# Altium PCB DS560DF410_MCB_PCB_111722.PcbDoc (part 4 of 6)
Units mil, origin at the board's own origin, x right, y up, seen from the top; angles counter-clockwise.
Board outline 5500 x 5000 mil, 6 copper layers (Top Layer, L2_GND1, L3_SIG1, L4_PWR1, L5_GND2, Bottom Layer), stack 61.748 mil thick; 297 components, 231 nets, 1236 pads, 998 vias.
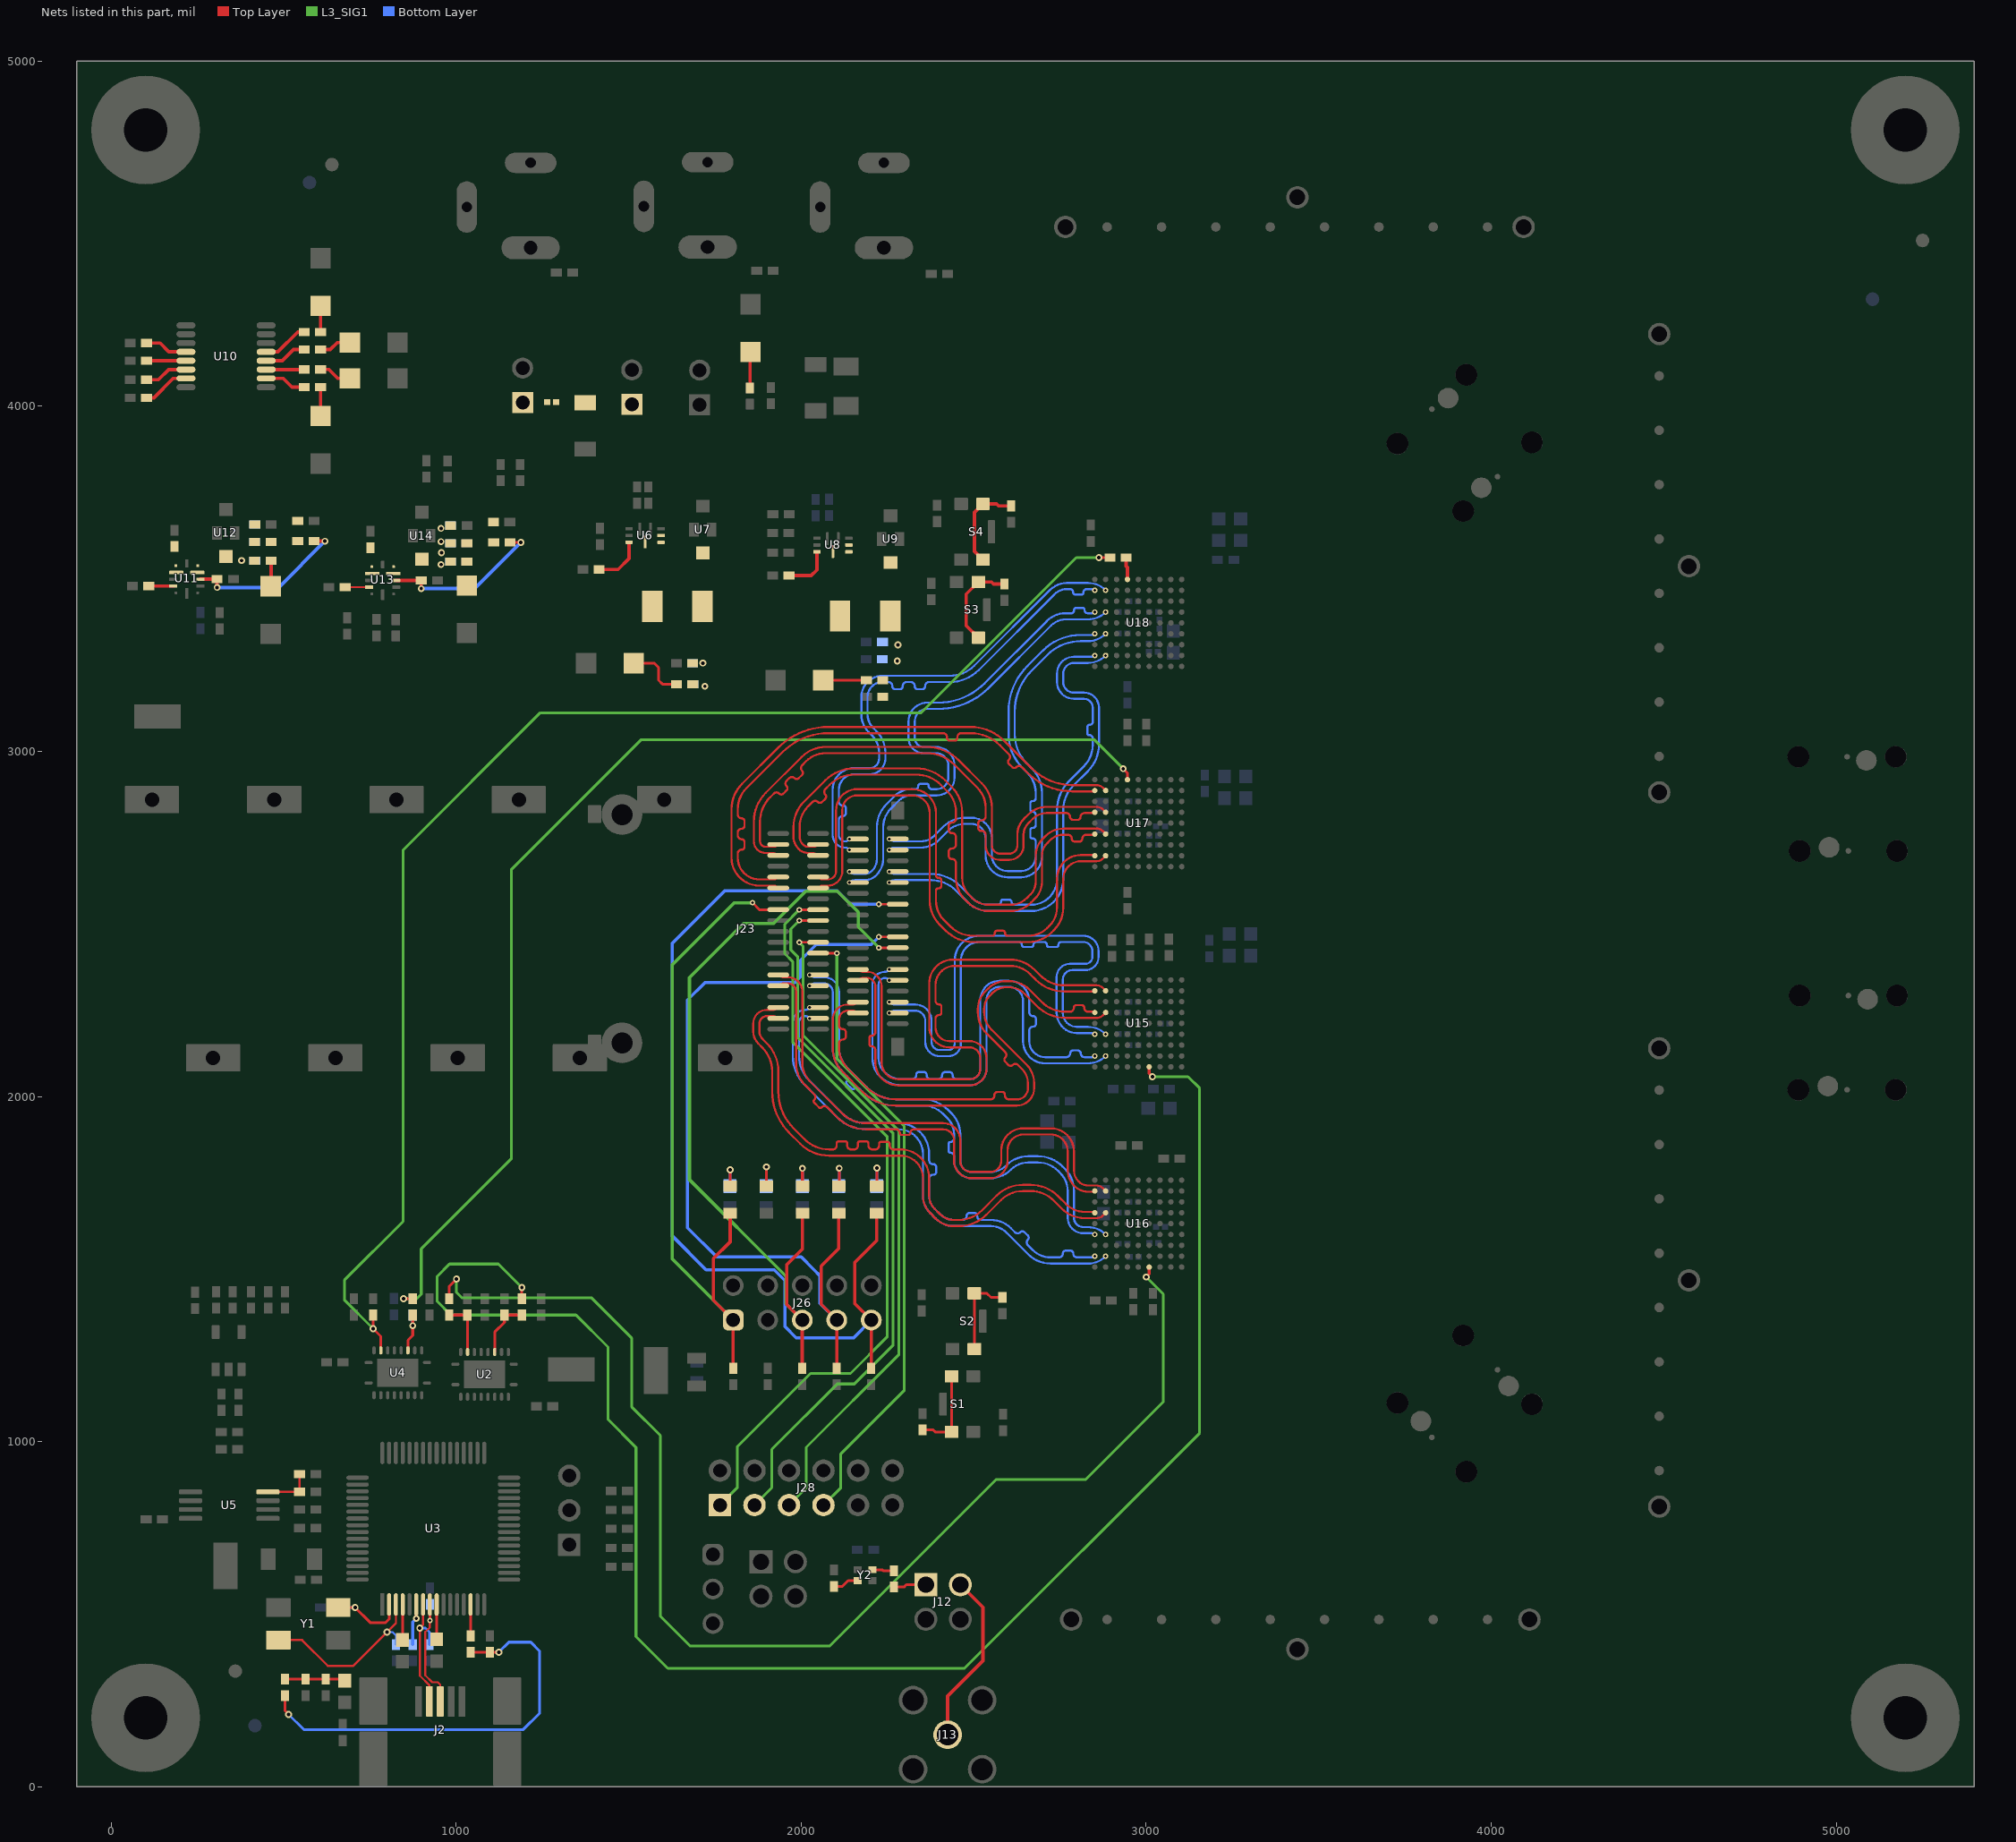
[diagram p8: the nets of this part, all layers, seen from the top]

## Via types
v1: diameter 20, hole 10, Top Layer to Bottom Layer, 380 vias
v2: diameter 24, hole 12, Top Layer to Bottom Layer, tented both sides, 226 vias
v3: diameter 20, hole 10, Top Layer to Bottom Layer, tented both sides, 162 vias
v4: diameter 14, hole 8.1, Top Layer to Bottom Layer, tented both sides, 88 vias
v5: diameter 16, hole 8.1, Top Layer to Bottom Layer, tented both sides, 84 vias
v6: diameter 16, hole 8, Top Layer to Bottom Layer, tented both sides, 34 vias
v7: diameter 15, hole 8.1, Top Layer to Bottom Layer, tented both sides, 16 vias
v8: diameter 19.68, hole 7.87, Top Layer to Bottom Layer, tented both sides, 8 vias

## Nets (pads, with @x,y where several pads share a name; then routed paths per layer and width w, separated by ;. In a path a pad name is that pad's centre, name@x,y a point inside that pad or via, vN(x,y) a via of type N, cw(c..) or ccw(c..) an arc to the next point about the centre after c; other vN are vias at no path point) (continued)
HOST_EGRESS_TX1N: J23.43 U17.J8 | length 1581.8
  Top Layer w6: J23.43@2049.02,2635.61 ccw(c2065.31,2651.9) 2065.31,2628.86 2077.2,2628.86 ccw(c2077.2,2652.96) 2101.3,2652.96 2101.3,2829.59 cw(c2162.06,2829.59) 2162.06,2890.35 2321.52,2890.35 cw(c2321.52,2821.12) 2390.75,2821.12 ; 2390.83,2821.12 2390.75,2821.12 ; 2399.1,2633.47 cw(c2399.1,2626.15) 2406.43,2626.15 2406.43,2610.77 cw(c2398.72,2610.77) 2398.72,2603.07 2397.41,2603.07 ccw(c2397.41,2596.41) 2390.75,2596.41 2390.75,2566.9 ccw(c2470.19,2566.9) 2414.02,2510.73 2431.96,2492.79 ccw(c2497.48,2558.3) 2497.48,2465.65 2554.38,2465.65 ccw(c2554.38,2472.14) 2560.86,2472.14 2560.86,2473 cw(c2568.19,2473) 2568.19,2480.32 2583.56,2480.32 cw(c2583.56,2472.62) 2591.26,2472.62 2591.26,2472.31 ccw(c2597.93,2472.31) 2597.93,2465.65 2659.2,2465.65 ccw(c2659.2,2541.64) 2712.93,2487.91 2720.13,2495.1 ccw(c2668.66,2546.58) 2741.45,2546.58 2741.45,2630.58 cw(c2810.52,2630.58) 2810.52,2699.65 2845.58,2699.65 cw(c2845.58,2691.96) U17.J8@2851.02,2697.39 ; 2399.1,2633.48 2397.24,2633.48 cw(c2397.24,2639.96) 2390.75,2639.96 2390.75,2821.12
HOST_EGRESS_TX1P: J23.44 U17.H8 | length 1581.3
  Top Layer w6: J23.44@2049.02,2604.11 cw(c2065.31,2587.82) 2065.31,2610.86 2077.2,2610.86 ccw(c2077.2,2652.96) 2119.3,2652.96 2119.3,2829.59 cw(c2162.06,2829.59) 2162.06,2872.35 2321.52,2872.35 cw(c2321.52,2821.12) 2372.75,2821.12 2372.75,2566.9 ccw(c2470.19,2566.9) 2401.28,2498.01 2419.24,2480.06 ccw(c2497.47,2558.3) 2497.47,2447.65 2659.2,2447.65 ccw(c2659.2,2541.64) 2725.66,2475.18 2732.86,2482.38 ccw(c2668.66,2546.58) 2759.45,2546.58 2759.45,2630.1 cw(c2810.99,2630.1) 2810.99,2681.65 2856.26,2681.65 ccw(c2856.26,2707) 2874.19,2689.07 U17.H8@2882.51,2697.39
HOST_EGRESS_TX2N: J23.40 U17.J6 | length 1582.2
  Top Layer w6: J23.40@2049.02,2730.09 cw(c2032.72,2746.39) 2032.72,2723.35 2020.83,2723.35 cw(c2020.83,2745.21) 2005.37,2729.75 cw(c2028.85,2753.23) 1995.65,2753.23 1995.65,2781.33 cw(c2079.41,2781.33) 2020.18,2840.56 2032.84,2853.21 cw(c2040.6,2845.45) 2048.36,2853.21 ccw(c2054.51,2859.36) 2060.66,2853.21 2070.12,2862.67 ccw(c2064.23,2868.56) 2070.12,2874.44 cw(c2078.15,2882.47) 2070.12,2890.49 2082.89,2903.26 cw(c2153.6,2832.55) 2153.6,2932.55 2333.73,2932.55 cw(c2333.73,2832.55) 2404.44,2903.26 2423.88,2883.82 ; 2423.88,2883.83 cw(c2364.3,2824.25) 2448.55,2824.25 2448.55,2804.5 cw(c2437.57,2804.5) 2437.57,2793.52 2436.57,2793.52 ccw(c2436.57,2784.82) 2427.88,2784.82 2427.88,2771.45 ccw(c2436.2,2771.45) 2436.2,2763.12 2437.2,2763.12 cw(c2437.2,2751.77) 2448.55,2751.77 2448.55,2729.38 cw(c2437.57,2729.38) 2437.57,2718.4 2436.57,2718.4 ccw(c2436.57,2709.7) 2427.88,2709.7 2427.88,2696.32 ccw(c2436.2,2696.32) 2436.2,2688 2437.2,2688 cw(c2437.2,2676.65) 2448.55,2676.65 2448.55,2633.25 ccw(c2537.05,2633.25) 2474.47,2570.67 2482.68,2562.46 ccw(c2543.43,2623.2) 2543.43,2537.3 2607.11,2537.3 ccw(c2607.11,2620.94) 2666.25,2561.8 2677.55,2573.09 ccw(c2628.59,2622.05) 2697.82,2622.05 2697.82,2698.44 cw(c2746.73,2698.44) 2712.15,2733.02 2721.39,2742.27 cw(c2759.7,2703.95) 2759.7,2758.13 2773.05,2758.13 cw(c2773.05,2746.78) 2784.4,2746.78 ccw(c2792.73,2746.78) 2792.73,2738.46 2806.1,2738.46 ccw(c2806.1,2747.16) 2814.8,2747.16 cw(c2825.77,2747.16) 2825.77,2758.13 2845.58,2758.13 ccw(c2845.58,2765.82) U17.J6@2851.02,2760.39
HOST_EGRESS_TX2P: J23.41 U17.H6 | length 1581.2
  Top Layer w6: J23.41@2049.02,2698.6 ccw(c2032.72,2682.31) 2032.72,2705.35 2020.83,2705.35 cw(c2020.83,2745.21) 1992.65,2717.02 cw(c2028.85,2753.23) 1977.65,2753.23 1977.65,2781.33 cw(c2079.41,2781.33) 2007.45,2853.28 2070.16,2915.99 cw(c2153.6,2832.55) 2153.6,2950.55 2333.73,2950.55 cw(c2333.73,2832.55) 2417.16,2915.99 2436.6,2896.55 cw(c2364.3,2824.25) 2466.55,2824.25 2466.55,2633.25 ccw(c2537.05,2633.25) 2487.2,2583.4 2495.41,2575.19 ccw(c2543.43,2623.2) 2543.43,2555.3 2607.11,2555.3 ccw(c2607.11,2620.93) 2653.52,2574.52 2664.82,2585.82 ccw(c2628.59,2622.05) 2679.82,2622.05 2679.82,2698.44 cw(c2746.73,2698.44) 2699.42,2745.75 2708.67,2755 cw(c2759.7,2703.97) 2759.7,2776.13 2856.26,2776.13 cw(c2856.26,2750.78) 2874.19,2768.71 U17.H6@2882.51,2760.39
HOST_EGRESS_TX3N: J23.2 U17.J4 | length 1582
  Top Layer w6: J23.2@1933.66,2730.09 cw(c1917.37,2746.39) 1917.37,2723.35 1896.85,2723.35 cw(c1896.85,2739.4) 1880.8,2739.4 1880.8,2796.2 cw(c1980.8,2796.2) 1910.09,2866.91 1920.68,2877.5 cw(c1928.44,2869.74) 1936.2,2877.5 ccw(c1942.35,2883.66) 1948.5,2877.5 1957.96,2886.96 ccw(c1952.07,2892.85) 1957.96,2898.73 cw(c1965.99,2906.76) 1957.96,2914.79 1965.51,2922.34 cw(c1973.27,2914.58) 1981.03,2922.34 ccw(c1987.19,2928.49) 1993.34,2922.34 2002.79,2931.8 ccw(c1996.91,2937.68) 2002.79,2943.57 cw(c2010.82,2951.59) 2002.79,2959.62 2014.17,2971 cw(c2071.04,2914.13) 2071.04,2994.55 2363.78,2994.55 cw(c2363.78,2881.15) 2443.96,2961.34 2510.74,2894.56 cw(c2452.83,2836.65) 2534.73,2836.65 2534.73,2810.95 ; 2521.75,2799.97 ccw(c2521.75,2791.27) 2513.05,2791.27 2513.05,2777.9 ccw(c2521.38,2777.9) 2521.38,2769.57 2523.38,2769.57 ; 2521.75,2799.98 2523.75,2799.98 ccw(c2523.75,2810.95) 2534.73,2810.95 ; 2523.38,2769.57 cw(c2523.37,2758.23) 2534.72,2758.23 2534.73,2727.43 ccw(c2576.7,2727.43) 2576.7,2685.45 2603.1,2685.45 ccw(c2603.1,2726.9) 2644.55,2726.9 2644.55,2758.9 cw(c2689.88,2758.9) 2657.83,2790.95 2671.3,2804.42 cw(c2711.62,2764.1) 2711.62,2821.13 2768.25,2821.13 cw(c2768.25,2810.15) 2779.23,2810.15 ccw(c2787.93,2810.15) 2787.93,2801.45 2801.3,2801.45 ccw(c2801.3,2809.78) 2809.62,2809.78 ; 2809.63,2809.78 cw(c2820.98,2809.78) 2820.98,2821.13 2845.58,2821.13 ccw(c2845.58,2828.81) U17.J4@2851.02,2823.38
HOST_EGRESS_TX3P: J23.3 U17.H4 | length 1581.1
  Top Layer w6: J23.3@1933.66,2698.6 ccw(c1917.37,2682.31) 1917.37,2705.35 1896.85,2705.35 cw(c1896.85,2739.4) 1862.8,2739.4 1862.8,2796.2 cw(c1980.8,2796.2) 1897.36,2879.64 2001.44,2983.72 ; 2001.45,2983.73 cw(c2071.04,2914.13) 2071.04,3012.55 2363.78,3012.55 cw(c2363.78,2881.15) 2456.69,2974.07 2523.47,2907.29 cw(c2452.83,2836.65) 2552.73,2836.65 2552.73,2727.43 ccw(c2576.7,2727.43) 2576.7,2703.45 2603.1,2703.45 ccw(c2603.1,2726.9) 2626.55,2726.9 2626.55,2758.9 cw(c2689.88,2758.9) 2645.1,2803.68 2658.57,2817.15 cw(c2711.62,2764.1) 2711.62,2839.13 2856.26,2839.13 cw(c2856.26,2813.77) 2874.19,2831.7 U17.H4@2882.51,2823.38
HOST_EGRESS_TX4N: J23.5 U17.J2 | length 1582.1
  Top Layer w6: 1816.07,2703.93 cw(c1827.05,2703.93) 1827.05,2714.9 ccw(c1827.05,2723.6) 1835.75,2723.6 1835.75,2736.98 ccw(c1827.42,2736.98) 1827.42,2745.3 cw(c1827.43,2756.65) 1816.08,2756.65 1816.07,2764.6 ; 1816.07,2764.6 cw(c1827.05,2764.6) 1827.05,2775.58 ccw(c1827.05,2784.27) 1835.75,2784.27 1835.75,2797.65 ccw(c1827.42,2797.65) 1827.42,2805.97 ; 1816.07,2703.93 1816.07,2691.73 ccw(c1878.95,2691.73) 1878.95,2628.86 1917.37,2628.86 ccw(c1917.37,2651.9) J23.5@1933.66,2635.61 ; 1827.42,2805.98 cw(c1827.43,2817.32) 1816.08,2817.32 1816.07,2831.69 cw(c1903.14,2831.69) 1841.57,2893.25 ; 1841.57,2893.25 1946.01,2997.68 cw(c2078.71,2864.97) 2078.71,3052.65 2411.38,3052.65 cw(c2411.38,3041.68) 2422.35,3041.68 2422.35,3039.68 ccw(c2431.05,3039.68) 2431.05,3030.98 2444.43,3030.98 ccw(c2444.43,3039.3) 2452.75,3039.3 2452.75,3041.3 cw(c2464.1,3041.3) 2464.1,3052.65 2490.61,3052.65 cw(c2490.61,2931.37) 2576.37,3017.13 2602.03,2991.47 cw(c2594,2983.44) 2602.03,2975.42 ccw(c2607.91,2969.53) 2602.03,2963.64 2611.48,2954.18 ccw(c2617.64,2960.34) 2623.79,2954.18 cw(c2631.55,2946.42) 2639.31,2954.18 2655.39,2938.1 ccw(c2785.72,3068.43) 2785.72,2884.12 2845.58,2884.12 ccw(c2845.58,2891.81) U17.J2@2851.02,2886.37
HOST_EGRESS_TX4P: J23.6 U17.H2 | length 1581.1
  Top Layer w6: J23.6@1933.66,2604.11 ccw(c1917.37,2587.82) 1917.37,2610.86 1878.95,2610.86 cw(c1878.95,2691.73) 1798.07,2691.73 1798.07,2831.69 cw(c1903.14,2831.69) 1828.85,2905.98 1933.28,3010.41 cw(c2078.71,2864.97) 2078.71,3070.65 2490.61,3070.65 cw(c2490.61,2931.37) 2589.09,3029.86 2668.12,2950.83 ccw(c2785.72,3068.43) 2785.72,2902.12 2856.26,2902.12 cw(c2856.26,2876.76) 2874.19,2894.69 U17.H2@2882.51,2886.37
HOST_EGRESS_TX5N: J23.34 U18.J8 | length 1434.9
  Bottom Layer w6: v4(2255.23,2651.35) ccw(c2271.52,2667.65) 2271.52,2644.61 2377.12,2644.61 cw(c2377.12,2526.61) 2460.55,2610.05 2495.41,2575.19 ccw(c2543.43,2623.2) 2543.43,2555.3 2569.85,2555.3 ccw(c2569.85,2564.8) 2579.35,2564.8 2579.35,2565 cw(c2584.52,2565) 2584.52,2570.18 2602.83,2570.18 cw(c2602.83,2563.26) 2609.75,2563.26 2609.75,2563.06 ccw(c2617.51,2563.06) 2617.51,2555.3 2666.67,2555.3 ccw(c2666.67,2630.08) 2741.45,2630.08 2741.45,2829.63 cw(c2859.45,2829.63) 2776.01,2913.06 2818.72,2955.78 ccw(c2755.43,3019.07) 2844.94,3019.07 2844.94,3037.33 ccw(c2835.44,3037.33) 2835.44,3046.83 2834.44,3046.83 cw(c2834.44,3052.01) 2829.26,3052.01 2829.26,3070.32 cw(c2836.18,3070.32) 2836.18,3077.23 2837.18,3077.23 ccw(c2837.18,3084.99) 2844.94,3084.99 2844.94,3127 ccw(c2819.94,3127) 2819.94,3152 2790,3152 cw(c2790,3200.55) 2741.45,3200.55 2741.45,3225 cw(c2790.5,3225) 2790.5,3274.05 2842.67,3274.05 ccw(c2842.67,3285.86) v7(2851.02,3277.51)
HOST_EGRESS_TX5P: J23.33 U18.H8 | length 1435.3
  Bottom Layer w6: v4(2255.23,2619.86) cw(c2271.52,2603.57) 2271.52,2626.61 2377.12,2626.61 cw(c2377.12,2526.61) 2447.83,2597.32 2482.69,2562.46 ccw(c2543.43,2623.2) 2543.43,2537.3 2666.67,2537.3 ccw(c2666.67,2630.08) 2759.45,2630.08 2759.45,2829.63 cw(c2859.45,2829.63) 2788.74,2900.34 2831.45,2943.05 ccw(c2755.43,3019.07) 2862.94,3019.07 2862.94,3127 ccw(c2819.94,3127) 2819.94,3170 2790,3170 cw(c2790,3200.55) 2759.45,3200.55 2759.45,3225 cw(c2790.5,3225) 2790.5,3256.05 2830.71,3256.05 ccw(c2830.71,3329.31) v7(2882.51,3277.51)
HOST_EGRESS_TX6N: J23.37 U18.J6 | length 1436
  Bottom Layer w6: v4(2255.23,2745.84) ccw(c2271.52,2762.13) 2271.52,2739.09 2347,2739.09 ccw(c2347,2793.72) 2385.63,2755.09 2412.32,2781.78 cw(c2474.47,2719.63) 2474.47,2807.53 2493.47,2807.53 cw(c2493.47,2748.27) 2552.73,2748.27 2552.73,2698.41 ccw(c2598.01,2698.41) 2598.01,2653.13 2637.56,2653.13 ccw(c2637.56,2695.39) 2679.82,2695.39 2679.82,2738.34 ccw(c2670.32,2738.34) 2670.32,2747.84 2669.32,2747.84 cw(c2669.32,2753.02) 2664.15,2753.02 2664.15,2771.32 cw(c2671.07,2771.32) 2671.07,2778.24 2672.07,2778.24 ccw(c2672.07,2786) 2679.83,2786 ; 2655.51,3246.77 ccw(c2787.15,3115.15) 2601,3115.15 2601,3049.82 ccw(c2739.38,3049.82) 2641.53,2951.97 2655.39,2938.1 cw(c2596.41,2879.12) 2679.82,2879.12 2679.82,2863.7 ; 2655.52,3246.78 2700.63,3291.89 cw(c2809.65,3182.87) 2809.65,3337.05 2842.67,3337.05 ccw(c2842.67,3348.85) v7(2851.02,3340.5) ; 2679.82,2786 2679.82,2816.04 ccw(c2670.32,2816.04) 2670.32,2825.54 2669.32,2825.54 cw(c2669.32,2830.72) 2664.15,2830.72 2664.15,2849.03 cw(c2671.07,2849.03) 2671.07,2855.94 2672.07,2855.94 ccw(c2672.07,2863.7) 2679.83,2863.7
HOST_EGRESS_TX6P: J23.36 U18.H6 | length 1434.8
  Bottom Layer w6: v4(2255.23,2714.35) cw(c2271.52,2698.06) 2271.52,2721.09 2347,2721.09 ccw(c2347,2793.72) 2398.35,2742.37 2425.04,2769.06 cw(c2474.47,2719.63) 2474.47,2789.53 2493.47,2789.53 cw(c2493.47,2748.27) 2534.72,2748.27 2534.73,2698.41 ccw(c2598.01,2698.41) 2598.01,2635.13 2637.56,2635.13 ccw(c2637.56,2695.39) 2697.82,2695.39 2697.82,2879.12 ccw(c2596.41,2879.12) 2668.12,2950.83 2654.26,2964.69 cw(c2739.39,3049.82) 2619,3049.82 2619,3115.15 cw(c2787.15,3115.15) 2668.25,3234.05 2713.36,3279.16 cw(c2809.65,3182.87) 2809.65,3319.05 2830.71,3319.05 ccw(c2830.71,3392.31) v7(2882.51,3340.5)
HOST_EGRESS_TX7N: J23.72 U18.J4 | length 1436
  Bottom Layer w6: v4(2139.87,2651.35) ccw(c2156.16,2667.65) 2156.16,2644.61 2182.72,2644.61 ccw(c2182.72,2676.68) 2205.4,2654 ccw(c2170.99,2688.4) 2219.65,2688.4 2219.65,2780.04 cw(c2313.96,2780.04) 2247.27,2846.73 2270.93,2870.38 cw(c2319.13,2822.17) 2319.13,2890.35 2331.24,2890.35 ccw(c2331.24,2898.11) 2339,2898.11 2339,2899.11 cw(c2345.92,2899.11) 2345.92,2906.03 2364.23,2906.03 cw(c2364.23,2900.85) 2369.4,2900.85 2369.4,2899.85 ccw(c2378.9,2899.85) 2378.9,2890.35 2392.76,2890.35 ccw(c2392.76,2924.12) 2426.53,2924.12 2426.53,2958.6 ccw(c2390.58,2958.6) 2390.58,2994.55 2355.32,2994.55 cw(c2355.32,3038.79) 2311.07,3038.79 2311.07,3086.27 cw(c2365.81,3086.27) 2365.81,3141 2396.88,3141 ccw(c2396.88,3330.8) 2531.09,3196.59 2711.89,3377.4 cw(c2766.55,3322.74) 2766.55,3400.04 2783.05,3400.04 ccw(c2783.05,3407.8) 2790.81,3407.8 2790.81,3408.8 cw(c2797.73,3408.8) 2797.73,3415.71 2816.04,3415.71 cw(c2816.04,3410.54) 2821.21,3410.54 2821.21,3409.54 ccw(c2830.71,3409.54) 2830.71,3400.04 2842.67,3400.04 ccw(c2842.67,3411.84) v7(2851.02,3403.5)
HOST_EGRESS_TX7P: J23.71 U18.H4 | length 1434.8
  Bottom Layer w6: v4(2139.87,2619.86) cw(c2156.16,2603.57) 2156.16,2626.61 2182.72,2626.61 ccw(c2182.72,2676.68) 2218.13,2641.27 ccw(c2170.99,2688.4) 2237.65,2688.4 2237.65,2780.04 cw(c2313.96,2780.04) 2260,2834 2283.65,2857.65 cw(c2319.13,2822.17) 2319.13,2872.35 2392.76,2872.35 ccw(c2392.76,2924.12) 2444.53,2924.12 2444.53,2958.6 ccw(c2390.58,2958.6) 2390.58,3012.55 2355.32,3012.55 cw(c2355.32,3038.79) 2329.08,3038.79 2329.07,3086.27 cw(c2365.81,3086.27) 2365.81,3123 2396.88,3123 ccw(c2396.88,3330.8) 2543.81,3183.85 2724.62,3364.67 cw(c2766.55,3322.74) 2766.55,3382.04 2830.71,3382.04 ccw(c2830.71,3455.3) v7(2882.51,3403.5)
HOST_EGRESS_TX8N: J23.75 U18.J2 | length 1434.8
  Bottom Layer w6: v4(2139.87,2745.84) 2137.27,2743.24 cw(c2127.26,2753.25) 2127.26,2739.09 cw(c2127.26,2756.37) 2115.05,2744.16 2114.79,2744.41 cw(c2128.55,2758.17) 2109.09,2758.17 2109.09,2801.37 cw(c2120.06,2801.37) 2120.06,2812.35 2121.06,2812.35 ccw(c2121.06,2821.05) 2129.76,2821.05 2129.76,2834.42 ccw(c2121.44,2834.42) 2121.44,2842.75 2120.44,2842.75 cw(c2120.44,2854.1) 2109.09,2854.1 2109.09,2888.29 cw(c2154.2,2888.29) 2154.2,2933.4 2198.03,2933.4 ccw(c2198.03,2979.37) 2244,2979.37 2244,2995.43 ccw(c2154.2,2995.43) 2217.7,3058.93 2208.5,3068.13 cw(c2247.2,3106.82) 2192.47,3106.82 2192.47,3157.62 cw(c2235.59,3157.62) 2235.59,3200.74 2253,3200.74 cw(c2253,3189.76) 2263.97,3189.76 2263.97,3188.76 ccw(c2272.68,3188.76) 2272.68,3180.06 2286.05,3180.06 ccw(c2286.05,3188.39) 2294.38,3188.39 2294.38,3189.39 cw(c2305.72,3189.39) 2305.72,3200.74 2318,3200.74 cw(c2318,3189.76) 2328.97,3189.76 2328.97,3188.76 ccw(c2337.68,3188.76) 2337.68,3180.06 2351.05,3180.06 ccw(c2351.05,3188.39) 2359.38,3188.39 2359.38,3189.39 cw(c2370.72,3189.39) 2370.72,3200.74 2430.91,3200.74 ccw(c2430.91,3318.74) 2514.34,3235.29 2733.94,3454.89 cw(c2770.29,3418.54) 2770.29,3469.95 2780,3469.95 cw(c2780,3462.19) 2787.76,3462.19 2787.76,3461.19 ccw(c2794.68,3461.19) 2794.68,3454.27 2812.98,3454.27 ccw(c2812.98,3459.45) 2818.16,3459.45 2818.16,3460.45 cw(c2827.66,3460.45) 2827.66,3469.95 2842.67,3469.95 cw(c2842.67,3458.14) v7(2851.02,3466.49)
HOST_EGRESS_TX8P: J23.74 U18.H2 | length 1435.6
  Bottom Layer w6: v4(2139.87,2714.35) 2137.27,2716.95 ccw(c2127.26,2706.94) 2127.26,2721.09 cw(c2127.26,2756.37) 2102.32,2731.43 2102.06,2731.69 cw(c2128.55,2758.17) 2091.09,2758.17 2091.09,2888.29 cw(c2154.2,2888.29) 2154.2,2951.4 2198.03,2951.4 ccw(c2198.03,2979.37) 2226,2979.37 2226,2995.43 ccw(c2154.2,2995.43) 2204.97,3046.2 2195.77,3055.4 cw(c2247.2,3106.82) 2174.47,3106.82 2174.47,3157.62 cw(c2235.59,3157.62) 2235.59,3218.74 2430.91,3218.74 ccw(c2430.91,3318.74) 2501.62,3248.03 2721.21,3467.62 cw(c2770.29,3418.54) 2770.29,3487.95 2830.71,3487.95 cw(c2830.71,3414.68) v7(2882.51,3466.49)
HOST_INGRESS_RX1N: J23.62 U15.A8 | length 1582.1
  Top Layer w6: J23.62@2164.37,2336.39 cw(c2180.66,2320.1) 2180.66,2343.14 2192.55,2343.14 cw(c2192.55,2324.64) 2205.63,2337.72 2208.96,2334.4 cw(c2193.96,2319.39) 2215.18,2319.39 2215.18,2186.95 cw(c2204.2,2186.95) 2204.2,2175.97 ; 2203.7,2175.97 ccw(c2203.7,2170.27) 2198,2170.27 2198,2150.9 ccw(c2203.32,2150.9) 2203.32,2145.57 2203.82,2145.57 ; 2203.7,2175.98 2204.2,2175.98 ; 2203.83,2145.57 cw(c2203.82,2134.23) 2215.17,2134.23 ; 2215.18,2134.23 2215.18,2098.03 ccw(c2280.95,2098.03) 2280.95,2032.25 2489.32,2032.25 ccw(c2489.32,2080.07) 2537.15,2080.07 2537.15,2111.03 ccw(c2487.86,2111.03) 2487.86,2160.32 2429.48,2160.32 cw(c2429.48,2200.6) 2389.21,2200.6 2389.21,2225 cw(c2400.19,2225) 2400.19,2235.98 ccw(c2400.19,2242.18) 2406.39,2242.18 2406.39,2260.55 ccw(c2400.56,2260.55) 2400.56,2266.37 ; 2400.56,2266.38 cw(c2400.56,2277.73) 2389.21,2277.73 2389.21,2322.3 cw(c2445.34,2322.3) 2445.34,2378.43 2605.54,2378.43 cw(c2605.54,2296.14) 2663.73,2354.33 ; 2663.73,2354.32 2679.49,2338.56 ccw(c2762.93,2422) 2762.93,2304 2845.58,2304 ccw(c2845.58,2311.69) U15.A8@2851.02,2306.25
HOST_INGRESS_RX1P: J23.63 U15.B8 | length 1581.1
  Top Layer w6: J23.63@2164.37,2367.89 ccw(c2180.66,2384.18) 2180.66,2361.14 2192.55,2361.14 cw(c2192.55,2324.64) 2218.36,2350.45 2221.69,2347.12 cw(c2193.96,2319.39) 2233.18,2319.39 2233.18,2098.03 ccw(c2280.95,2098.03) 2280.95,2050.25 2489.32,2050.25 ccw(c2489.32,2080.07) 2519.15,2080.07 2519.15,2111.03 ccw(c2487.86,2111.03) 2487.86,2142.32 2429.48,2142.32 cw(c2429.48,2200.59) 2371.21,2200.59 2371.21,2327.65 cw(c2439.99,2327.65) 2439.99,2396.43 2605.54,2396.43 cw(c2605.54,2296.14) 2676.45,2367.05 2692.22,2351.29 ccw(c2762.93,2422) 2762.93,2322 2856.26,2322 cw(c2856.26,2296.64) 2874.19,2314.57 U15.B8@2882.51,2306.25
HOST_INGRESS_RX2N: J23.59 U15.A6 | length 1581
  Top Layer w6: 2109.62,2153.52 2109.62,2140.52 ccw(c2190.66,2140.52) 2133.36,2083.21 2189.87,2026.71 ccw(c2274.74,2111.58) 2274.74,1991.55 2549.12,1991.55 ccw(c2549.12,2002.52) 2560.1,2002.52 2560.1,2004.52 cw(c2568.8,2004.52) 2568.8,2013.22 2582.18,2013.22 cw(c2582.18,2004.9) 2590.5,2004.9 2590.5,2002.9 ccw(c2601.85,2002.9) 2601.85,1991.55 2625.01,1991.55 ccw(c2625.01,2023.69) 2657.15,2023.69 2657.15,2038.94 ccw(c2600.09,2038.94) 2640.44,2079.29 2628.74,2090.99 ccw(c2620.71,2082.96) 2612.69,2090.99 cw(c2606.8,2096.87) 2600.91,2090.99 2591.46,2100.45 cw(c2597.61,2106.6) 2591.46,2112.75 ccw(c2583.69,2120.51) 2591.46,2128.27 2538.41,2181.31 cw(c2602.05,2244.95) 2512.05,2244.95 2512.05,2253.3 cw(c2582.97,2253.3) 2532.82,2303.45 2542.67,2313.31 cw(c2593.3,2262.68) 2593.3,2334.28 2602.05,2334.27 ; 2109.63,2153.52 cw(c2120.98,2153.52) 2120.97,2164.87 ; 2120.6,2195.27 cw(c2120.6,2186.57) 2129.3,2186.57 2129.3,2173.2 cw(c2120.97,2173.2) 2120.97,2164.88 ; 2120.6,2195.28 cw(c2120.6,2206.25) 2109.62,2206.25 2109.62,2222.55 cw(c2135.73,2222.55) 2135.73,2248.65 2148.08,2248.65 cw(c2148.08,2225.61) J23.59@2164.37,2241.91 ; 2602.05,2334.27 cw(c2602.05,2251.27) 2660.74,2309.96 2695.82,2274.89 ccw(c2766.74,2345.81) 2766.74,2245.51 2778.98,2245.51 ccw(c2778.98,2256.86) 2790.33,2256.86 ; 2790.5,2258 cw(c2797.19,2258) 2797.19,2264.69 2812.53,2264.69 cw(c2812.53,2256.49) 2820.73,2256.49 ccw(c2831.7,2256.49) 2831.7,2245.51 2845.58,2245.51 cw(c2845.58,2237.82) U15.A6@2851.02,2243.26
HOST_INGRESS_RX2P: J23.60 U15.B6 | length 1581.4
  Top Layer w6: J23.60@2164.37,2273.4 cw(c2148.08,2289.69) 2148.08,2266.65 2135.73,2266.65 ccw(c2135.73,2222.55) 2091.62,2222.55 2091.62,2140.52 ccw(c2190.66,2140.52) 2120.63,2070.49 2177.14,2013.98 ; 2177.15,2013.97 ccw(c2274.74,2111.58) 2274.74,1973.55 2625.01,1973.55 ccw(c2625.01,2023.69) 2675.15,2023.69 2675.15,2038.94 ccw(c2600.09,2038.94) 2653.17,2092.01 2551.14,2194.04 cw(c2602.05,2244.95) 2530.05,2244.95 2530.05,2253.3 cw(c2582.97,2253.3) 2545.55,2290.73 ; 2545.55,2290.73 2555.4,2300.58 cw(c2593.3,2262.68) 2593.3,2316.28 2602.05,2316.27 cw(c2602.05,2251.27) 2648.02,2297.23 2683.09,2262.16 ccw(c2766.74,2345.81) 2766.74,2227.51 2856.26,2227.51 ccw(c2856.26,2252.87) 2874.19,2234.94 U15.B6@2882.51,2243.26
HOST_INGRESS_RX3N: J23.21 U15.A4 | length 1436
  Bottom Layer w6: v4(2255.23,2241.91) cw(c2271.52,2225.61) 2271.52,2248.65 2330.16,2248.65 cw(c2330.16,2219.11) 2359.7,2219.11 2359.7,2158.1 ccw(c2401.1,2158.1) 2401.1,2116.7 2426.9,2116.7 ccw(c2426.9,2152.7) 2462.9,2152.7 2462.9,2393.87 cw(c2516.68,2393.87) 2516.68,2447.65 2631.4,2447.65 cw(c2631.4,2439.34) 2639.71,2439.34 2639.71,2438.64 ccw(c2645.07,2438.64) 2645.07,2433.27 2667.78,2433.27 ccw(c2667.78,2438.64) 2673.15,2438.64 2673.15,2439.34 cw(c2681.46,2439.34) 2681.46,2447.65 2703.86,2447.65 cw(c2703.86,2439.34) 2712.16,2439.34 2712.16,2438.68 ccw(c2717.86,2438.68) 2717.86,2432.98 2739.91,2432.98 ccw(c2739.91,2438.68) 2745.61,2438.68 2745.61,2439.34 cw(c2753.91,2439.34) 2753.91,2447.65 2817.28,2447.65 cw(c2817.28,2420.93) 2844,2420.93 2844,2404.72 cw(c2823.46,2404.72) 2823.46,2384.18 2778.65,2384.18 ccw(c2778.65,2346.01) 2740.47,2346.01 ; 2740.48,2346.01 2740.48,2242.08 ccw(c2798.83,2242.08) 2798.83,2183.73 2842.67,2183.73 cw(c2842.67,2171.92) v7(2851.02,2180.27)
HOST_INGRESS_RX3P: J23.22 U15.B4 | length 1434.8
  Bottom Layer w6: v4(2255.23,2273.4) ccw(c2271.52,2289.69) 2271.52,2266.65 2330.16,2266.65 cw(c2330.16,2219.11) 2377.7,2219.11 2377.7,2158.1 ccw(c2401.1,2158.1) 2401.1,2134.7 2426.9,2134.7 ccw(c2426.9,2152.7) 2444.9,2152.7 2444.9,2393.87 cw(c2516.68,2393.87) 2516.68,2465.65 2817.28,2465.65 cw(c2817.28,2420.93) 2862,2420.93 2862,2404.72 cw(c2823.46,2404.72) 2823.46,2366.18 2786.1,2366.18 ccw(c2786.1,2338.56) 2758.47,2338.56 ; 2758.48,2338.56 2758.48,2242.08 ccw(c2798.83,2242.08) 2798.83,2201.73 2830.71,2201.73 cw(c2830.71,2128.46) v7(2882.51,2180.27)
HOST_INGRESS_RX4N: J23.24 U15.A2 | length 1435.3
  Bottom Layer w6: v4(2255.23,2336.39) 2252.62,2339 ccw(c2242.62,2328.99) 2242.62,2343.14 ccw(c2242.62,2325.86) 2230.4,2338.08 2230.14,2337.82 ccw(c2243.9,2324.06) 2224.44,2324.06 2224.44,2110.84 ccw(c2280.53,2110.84) 2240.87,2071.18 ccw(c2291.41,2121.72) 2291.41,2050.25 2322.04,2050.25 ccw(c2322.04,2061.6) 2333.39,2061.6 2333.39,2062.6 cw(c2341.72,2062.6) 2341.72,2070.93 2355.09,2070.93 cw(c2355.09,2062.23) 2363.79,2062.23 2363.79,2061.23 ccw(c2374.77,2061.23) 2374.77,2050.25 2397.17,2050.25 ccw(c2397.17,2061.6) 2408.52,2061.6 2408.52,2062.3 cw(c2416.84,2062.3) 2416.84,2070.62 2430.22,2070.62 cw(c2430.22,2061.93) 2438.92,2061.93 2438.92,2061.23 ccw(c2449.89,2061.23) 2449.89,2050.25 2489.32,2050.25 ccw(c2489.32,2080.07) 2519.15,2080.07 2519.15,2278.91 cw(c2575.54,2278.91) 2575.54,2335.3 2602.24,2335.3 cw(c2602.24,2276.47) 2661.06,2276.47 2661.06,2243.82 ccw(c2672.04,2243.82) 2672.04,2232.85 cw(c2672.04,2224.45) 2680.44,2224.45 2680.44,2210.48 cw(c2672.41,2210.48) 2672.41,2202.45 ccw(c2672.41,2191.1) 2661.06,2191.1 2661.06,2160.01 ccw(c2707.26,2160.01) 2707.26,2113.82 2768.47,2113.82 ccw(c2768.47,2125.17) 2779.82,2125.17 cw(c2788.14,2125.17) 2788.14,2133.49 2801.52,2133.49 cw(c2801.52,2124.79) 2810.22,2124.79 ccw(c2821.19,2124.79) 2821.19,2113.82 2842.67,2113.82 ccw(c2842.67,2125.62) v7(2851.02,2117.28)
HOST_INGRESS_RX4P: J23.25 U15.B2 | length 1435.3
  Bottom Layer w6: v4(2255.23,2367.89) 2252.62,2365.29 cw(c2242.62,2375.29) 2242.62,2361.14 ccw(c2242.62,2325.86) 2217.67,2350.81 2217.42,2350.55 ccw(c2243.9,2324.06) 2206.44,2324.06 2206.44,2110.84 ccw(c2280.53,2110.84) 2228.14,2058.46 ccw(c2291.41,2121.72) 2291.41,2032.25 2489.32,2032.25 ccw(c2489.32,2080.07) 2537.15,2080.07 2537.15,2278.91 cw(c2575.54,2278.91) 2575.54,2317.3 2602.24,2317.3 cw(c2602.24,2276.47) 2643.06,2276.47 2643.06,2160.02 ccw(c2707.26,2160.02) 2707.26,2095.82 2830.71,2095.82 ccw(c2830.71,2169.08) v7(2882.51,2117.28)
HOST_INGRESS_RX5N: J23.15 U16.A8 | length 1581.3
  Top Layer w6: J23.15@1933.66,2320.65 cw(c1949.95,2304.35) 1949.95,2327.39 1961.84,2327.39 cw(c1961.84,2303.91) 1985.32,2303.91 1985.32,2096.42 ccw(c2076.09,2096.42) 2011.91,2032.23 2038.14,2006 cw(c2030.38,1998.24) 2038.14,1990.48 2037.79,1990.13 ccw(c2041.82,1986.1) 2037.79,1982.06 2051.49,1968.36 ccw(c2055.26,1972.13) 2059.02,1968.36 2059.38,1968.72 cw(c2067.4,1960.69) 2075.43,1968.72 2104.9,1939.24 ccw(c2188.29,2022.62) 2188.29,1904.7 2275.48,1904.7 cw(c2275.48,1894.19) 2286,1894.19 2286,1894.05 ccw(c2291.32,1894.05) 2291.32,1888.73 2311.4,1888.73 ccw(c2311.4,1893.73) 2316.4,1893.73 cw(c2327.38,1893.73) 2327.38,1904.7 2411.42,1904.7 cw(c2411.42,1873.1) 2443.02,1873.1 2443.02,1813.77 ccw(c2493.47,1813.77) 2493.47,1763.32 2547.85,1763.32 ccw(c2547.85,1813.47) 2598,1813.47 2598,1843.86 cw(c2643.84,1843.86) 2643.84,1889.7 2723.39,1889.7 cw(c2723.39,1840.55) 2772.55,1840.55 2772.55,1785.88 ccw(c2835.64,1785.88) 2791.03,1741.27 2791.62,1740.67 ccw(c2832.16,1781.21) 2832.16,1723.88 2845.58,1723.88 ccw(c2845.58,1731.57) U16.A8@2851.02,1726.13
HOST_INGRESS_RX5P: J23.14 U16.B8 | length 1579.3
  Top Layer w6: J23.14@1933.66,2352.14 ccw(c1949.95,2368.43) 1949.95,2345.39 1961.84,2345.39 cw(c1961.84,2303.91) 2003.32,2303.91 2003.32,2096.42 ccw(c2076.09,2096.42) 2024.64,2044.96 2117.61,1951.99 ccw(c2188.32,2022.7) 2188.32,1922.7 2411.42,1922.7 cw(c2411.42,1873.1) 2461.02,1873.1 2461.02,1813.77 ccw(c2493.47,1813.77) 2493.47,1781.32 2547.85,1781.32 ccw(c2547.85,1813.47) 2580,1813.47 2580,1843.86 cw(c2643.84,1843.86) 2643.84,1907.7 2723.39,1907.7 cw(c2723.39,1840.55) 2790.55,1840.55 2790.55,1785.88 ccw(c2835.64,1785.88) 2803.76,1753.99 2804.35,1753.4 ccw(c2832.16,1781.21) 2832.16,1741.88 2856.26,1741.88 cw(c2856.26,1716.53) 2874.19,1734.45 U16.B8@2882.51,1726.13
HOST_INGRESS_RX6N: J23.18 U16.A6 | length 1581.8
  Top Layer w6: J23.18@1933.66,2226.16 ccw(c1917.37,2209.87) 1917.37,2232.91 1900.72,2232.91 ccw(c1900.72,2211.21) 1879.03,2211.21 1879.03,2188.03 ccw(c1909.44,2188.03) 1887.93,2166.52 1900.51,2153.94 cw(c1819.73,2073.15) 1933.97,2073.15 1933.97,2013.75 ccw(c2083.46,2013.75) 1977.76,1908.04 2009.86,1875.94 ccw(c2080.57,1946.65) 2080.57,1846.65 2091.95,1846.65 ccw(c2091.95,1857.62) 2102.92,1857.62 2102.93,1864.12 cw(c2108.62,1864.12) 2108.62,1869.82 2128,1869.82 cw(c2128,1864.5) 2133.33,1864.5 2133.32,1858 ; 2133.33,1858 ccw(c2144.68,1858) 2144.68,1846.65 2153.32,1846.65 ccw(c2153.32,1857.62) 2164.3,1857.62 2164.3,1864.12 cw(c2170,1864.12) 2170,1869.82 2189.38,1869.82 cw(c2189.38,1864.5) 2194.7,1864.5 2194.7,1858 ccw(c2206.05,1858) 2206.05,1846.65 2214.95,1846.65 ccw(c2214.95,1857.62) 2225.92,1857.62 2225.93,1862.62 cw(c2231.62,1862.62) 2231.62,1868.32 2251,1868.32 cw(c2251,1863) 2256.33,1863 2256.32,1858 ; 2256.33,1858 ccw(c2267.68,1858) 2267.68,1846.65 2288.2,1846.65 cw(c2288.2,1764) 2370.85,1764 2370.85,1712.47 ccw(c2423.34,1712.47) 2386.22,1675.35 2402.4,1659.17 ccw(c2442.77,1699.54) 2442.77,1642.45 2457.2,1642.45 ccw(c2457.2,1736.95) 2524.02,1670.13 2566.52,1712.63 ; 2566.53,1712.63 cw(c2642.27,1636.87) 2642.27,1744 2664.62,1744 cw(c2664.62,1630.44) 2744.92,1710.74 2767.68,1687.99 ccw(c2822.22,1742.53) 2822.22,1665.39 2845.58,1665.39 cw(c2845.58,1657.7) U16.A6@2851.02,1663.14
HOST_INGRESS_RX6P: J23.17 U16.B6 | length 1581.6
  Top Layer w6: J23.17@1933.66,2257.65 cw(c1917.37,2273.94) 1917.37,2250.91 1900.72,2250.91 ccw(c1900.72,2211.21) 1861.03,2211.21 1861.03,2188.02 ccw(c1909.44,2188.02) 1875.21,2153.79 1887.78,2141.21 cw(c1819.73,2073.16) 1915.97,2073.16 1915.97,2013.75 ccw(c2083.46,2013.75) 1965.02,1895.32 ; 1965.03,1895.32 1997.14,1863.21 ccw(c2080.57,1946.65) 2080.57,1828.65 2288.2,1828.65 cw(c2288.2,1764) 2352.85,1764 2352.85,1712.47 ccw(c2423.34,1712.47) 2373.5,1662.62 2389.68,1646.44 ccw(c2442.77,1699.54) 2442.77,1624.45 2457.2,1624.45 ccw(c2457.2,1736.95) 2536.75,1657.4 2579.24,1699.89 cw(c2642.28,1636.85) 2642.28,1726 2664.62,1726 cw(c2664.62,1630.44) 2732.19,1698.01 2754.95,1675.26 ccw(c2822.22,1742.53) 2822.22,1647.39 2856.26,1647.39 ccw(c2856.26,1672.75) 2874.19,1654.82 U16.B6@2882.51,1663.14
HOST_INGRESS_RX7N: J23.53 U16.A4 | length 1434.3
  Bottom Layer w6: v4(2024.52,2320.65) cw(c2040.81,2304.35) 2040.81,2327.39 2066.5,2327.39 cw(c2066.5,2302.27) 2091.62,2302.27 2091.62,2140.52 ccw(c2190.66,2140.52) 2120.63,2070.49 2131.84,2059.28 cw(c2124.08,2051.52) 2131.84,2043.76 ccw(c2135.16,2040.44) 2131.83,2037.12 2146.95,2022 ccw(c2150.01,2025.06) 2153.07,2022 cw(c2161.09,2013.97) 2169.12,2022 2177.26,2013.86 ccw(c2274.58,2111.18) 2274.58,1973.55 2352,1973.55 cw(c2352,1887.48) 2412.86,1948.34 2423.21,1937.99 cw(c2375.38,1890.15) 2443.03,1890.15 ; 2443.02,1878.88 2443.02,1890.15 ; 2443.03,1878.88 cw(c2432.05,1878.88) 2432.05,1867.9 ccw(c2432.05,1863.2) 2427.35,1863.2 2427.35,1841.83 ccw(c2431.68,1841.83) 2431.67,1837.5 cw(c2431.67,1826.15) 2443.02,1826.15 2443.02,1814.14 ccw(c2494,1814.14) 2494,1763.17 2547.67,1763.17 ccw(c2547.67,1848.59) 2608.07,1788.19 2608.16,1788.27 cw(c2657.6,1738.82) 2657.6,1808.75 2686.12,1808.75 cw(c2686.12,1726) 2744.63,1784.52 2751.15,1778 cw(c2699.47,1726.33) 2772.55,1726.33 2772.55,1648.66 ccw(c2817.6,1648.66) 2817.6,1603.61 2842.67,1603.61 cw(c2842.67,1591.8) v7(2851.02,1600.15)
HOST_INGRESS_RX7P: J23.52 U16.B4 | length 1434.9
  Bottom Layer w6: v4(2024.52,2352.14) ccw(c2040.81,2368.43) 2040.81,2345.39 2066.5,2345.39 cw(c2066.5,2302.27) 2109.62,2302.27 2109.62,2140.52 ccw(c2190.66,2140.52) 2133.36,2083.21 2189.99,2026.59 ccw(c2274.58,2111.18) 2274.58,1991.55 2352,1991.55 cw(c2352,1887.48) 2425.59,1961.07 2435.94,1950.72 cw(c2375.37,1890.15) 2461.02,1890.15 2461.02,1814.14 ccw(c2494,1814.14) 2494,1781.17 2547.67,1781.17 ccw(c2547.67,1848.59) 2595.34,1800.92 2595.43,1801 cw(c2657.6,1738.82) 2657.6,1826.75 2686.43,1826.75 cw(c2686.43,1726.75) 2757.14,1797.46 2763.87,1790.73 cw(c2699.47,1726.33) 2790.55,1726.33 2790.55,1648.66 ccw(c2817.6,1648.66) 2817.6,1621.61 2830.71,1621.61 cw(c2830.71,1548.35) v7(2882.51,1600.15)
HOST_INGRESS_RX8N: J23.56 U16.A2 | length 1435.2
  Bottom Layer w6: v4(2024.52,2226.16) 2021.92,2228.76 ccw(c2011.91,2218.75) 2011.91,2232.91 ccw(c2011.91,2215.63) 1999.69,2227.85 1999.43,2227.59 ccw(c2013.2,2213.83) 1993.73,2213.83 1993.73,2117.29 ccw(c2093.73,2117.29) 2023.02,2046.58 2117.61,1951.99 ccw(c2188.32,2022.7) 2188.32,1922.7 2281.89,1922.7 cw(c2281.89,1833.75) 2370.85,1833.75 2370.85,1815.01 ccw(c2382.2,1815.01) 2382.2,1803.66 2383.2,1803.66 cw(c2383.2,1795.33) 2391.52,1795.33 2391.53,1781.96 cw(c2382.82,1781.96) 2382.82,1773.26 2381.82,1773.26 ccw(c2381.82,1762.28) 2370.85,1762.28 2370.85,1712.47 ccw(c2423.34,1712.47) 2386.22,1675.35 2402.4,1659.17 ccw(c2442.77,1699.54) 2442.77,1642.45 2468.42,1642.45 ccw(c2468.42,1653.8) 2479.77,1653.8 2479.77,1654.3 cw(c2488.1,1654.3) 2488.1,1662.62 2501.47,1662.62 cw(c2501.47,1653.93) 2510.17,1653.93 2510.17,1653.43 ccw(c2521.15,1653.43) 2521.15,1642.45 2549.55,1642.45 cw(c2549.55,1559.76) 2608.02,1618.24 2619.54,1606.71 ccw(c2627.57,1614.74) 2635.59,1606.71 cw(c2641.48,1600.82) 2647.37,1606.71 2656.82,1597.25 ; 2656.82,1569.43 2670.65,1555.6 ccw(c2723.53,1608.49) 2723.53,1533.7 2747,1533.7 ccw(c2747,1545.05) 2758.35,1545.05 cw(c2766.68,1545.05) 2766.68,1553.37 2780.05,1553.37 cw(c2780.05,1544.67) 2788.75,1544.67 ccw(c2799.73,1544.67) 2799.73,1533.7 2842.67,1533.7 ccw(c2842.67,1545.5) v7(2851.02,1537.16) ; 2656.83,1569.43 cw(c2664.59,1577.19) 2656.83,1584.95 ccw(c2650.67,1591.1) 2656.83,1597.25
HOST_INGRESS_RX8P: J23.55 U16.B2 | length 1435.2
  Bottom Layer w6: v4(2024.52,2257.65) 2021.92,2255.05 cw(c2011.91,2265.06) 2011.91,2250.91 ccw(c2011.91,2215.63) 1986.96,2240.57 1986.71,2240.31 ccw(c2013.2,2213.83) 1975.73,2213.83 1975.73,2117.29 ccw(c2093.73,2117.29) 2010.29,2033.85 2104.89,1939.26 ccw(c2188.32,2022.7) 2188.32,1904.7 2281.89,1904.7 cw(c2281.89,1833.75) 2352.85,1833.75 2352.85,1712.47 ccw(c2423.34,1712.47) 2373.5,1662.62 2389.68,1646.44 ccw(c2442.77,1699.54) 2442.77,1624.45 2549.55,1624.45 cw(c2549.55,1559.76) 2595.29,1605.51 2657.92,1542.88 ; 2657.93,1542.87 ccw(c2723.53,1608.49) 2723.53,1515.7 2830.71,1515.7 ccw(c2830.71,1588.96) v7(2882.51,1537.16)
INT_N_1: R62.1 U15.F1 | length 4951.3
  Top Layer w8: R62.1@1190.55,1414.04 v3(1190.55,1446.33) ; U15.F1@3008.5,2085.78 3008.5,2066.6 v3(3017.88,2057.23)
  L3_SIG1 w8: v3(1190.55,1446.33) 1122.43,1514.45 980.95,1514.45 945,1478.5 945,1406.7 984.9,1366.8 1347.3,1366.8 1440.3,1273.8 1440.3,1064.2 1521.4,983.1 1521.4,435.2 1613.5,343.1 2473.2,343.1 3154.7,1024.6 3154.7,2023.72 3121.2,2057.23 v3(3017.88,2057.23)
INT_N_1_LS: R61.1 R62.2 U2.4 | length 169.3
  Top Layer w8: U2.4@1111.98,1259.61 1111.98,1317.08 1140.1,1345.2 R61.1@1140.1,1366.79 R62.2@1190.55,1366.79
INT_N_2: R72.1 U16.F1 | length 3708.3
  Top Layer w8: R72.1@979.78,1414.04 979.78,1449.68 v3(1001.12,1471.03) ; v3(3000.15,1476.9) 3008.5,1485.25 U16.F1@3008.5,1505.66
  L3_SIG1 w8: v3(1001.12,1471.03) 1001.12,1431.97 1016.11,1416.99 1391.81,1416.99 1508.5,1300.3 1508.5,1101.1 1591.82,1017.78 1591.82,494.07 1678,407.9 2082.7,407.9 2565.5,890.7 2825.1,890.7 3049.55,1115.15 3049.55,1427.5 v3(3000.15,1476.9)
INT_N_2_LS: R71.1 R72.2 U2.8 | length 160.2
  Top Layer w8: R72.2@979.78,1366.79 R71.1@1032.4,1366.79 1033.24,1365.95 U2.8@1033.24,1259.61
INT_N_3: R82.1 U17.F1 | length 3422.6
  Top Layer w8: v3(847.56,1414.04) R82.1@874.4,1414.04 ; v3(2933.15,2949.48) 2945.5,2937.12 U17.F1@2945.5,2917.87
  L3_SIG1 w8: v3(847.56,1414.04) 885.99,1414.04 898.88,1426.92 898.88,1558.18 1159.81,1819.11 1159.81,2656.93 1536.57,3033.7 2848.93,3033.7 v3(2933.15,2949.48)
INT_N_3_LS: R81.1 R82.2 U4.4 | length 139.1
  Top Layer w8: U4.4@860.54,1264.39 860.54,1293.81 874.4,1307.67 v3(874.4,1335.86) R82.2@874.4,1366.79
  Bottom Layer w8: v3(874.4,1335.86) R81.1@874.4,1366.79
INT_N_4: R92.1 U18.F1 | length 64.7
  Top Layer w10: R92.1@2942.02,3561.25 2942.02,3535.98 2945.5,3532.5 U18.F1@2945.5,3497.98
INT_N_4_LS: R91.1 R92.2 U4.8 | length 4002.7
  Top Layer w8: R91.1@759.52,1366.79 v3(759.52,1327.2) 781.8,1304.92 U4.8@781.8,1264.39 ; v3(2863,3561.25) R92.2@2894.78,3561.25
  L3_SIG1 w8: v3(759.52,1327.2) 676.2,1410.53 676.2,1467.68 846.62,1638.1 846.62,2714.18 1244.15,3111.7 2347.9,3111.7 2797.45,3561.25 v3(2863,3561.25)
IntL/RxLOS: D13.2 J23.28 J26.7 R98.1 | length 2451.1
  Top Layer w7.3: v6(2225.22,2462.38) J23.28@2279.72,2462.38
  Top Layer w9.4: R98.1@2103.16,1212.48 J26.7@2103.16,1352.15 2057.8,1397.51 2057.8,1508.43 2109.09,1559.72 D13.2@2109.09,1661.5
  Bottom Layer w9.4: J26.7@2103.16,1352.15 2054.88,1400.43 2054.88,1480.28 2036.42,1498.73 2000.15,1535 1810.5,1535 1755.6,1535 1670.8,1619.8 1670.8,2279.68 1720.75,2329.62 1980.85,2329.62 1997.4,2346.18 1997.4,2393.3 2044.1,2440 2202.84,2440 v6(2225.22,2462.38)
LPMode/TxDis: D14.2 J23.31 J26.9 R95.1 | length 2873
  Top Layer w7.3: v6(2225.22,2556.87) J23.31@2279.72,2556.87
  Top Layer w9.4: R95.1@2203.16,1212.48 J26.9@2203.16,1352.15 2155.72,1399.58 2155.72,1519.25 2219.09,1582.62 D14.2@2219.09,1661.5
  Bottom Layer w9.4: J26.9@2203.16,1352.15 2151.97,1300.95 1985.78,1300.95 1953.32,1333.4 1953.32,1466.4 1921.72,1498 1724.5,1498 1626.82,1595.68 1626.82,2444.12 1778.8,2596.1 2104.19,2596.1 2143.42,2556.87 v6(2225.22,2556.87)
ModPrsL: D12.2 J23.27 J26.5 R97.1 | length 2415
  Top Layer w7.3: v6(2225.22,2430.88) J23.27@2279.72,2430.88
  Top Layer w9.4: R97.1@2003.16,1212.48 J26.5@2003.16,1352.15 1958.07,1397.23 1958.07,1512.62 2004.09,1558.64 D12.2@2004.09,1661.5
  L3_SIG1 w9.4: J26.5@2003.16,1352.15 1955.32,1399.98 1955.32,1479.55 1676.19,1758.69 1676.19,2344.44 1832.95,2501.2 1920.12,2501.2 2013.6,2594.68 2104.9,2594.68 2165.51,2534.06 2165.51,2490.59 v6(2225.22,2430.88)
ModSelL: D10.2 J23.8 J26.1 R96.1 | length 1985
  Top Layer w7.3: v6(1859.16,2561.12) 1879.16,2541.12 J23.8@1933.66,2541.12
  Top Layer w9.4: D10.2@1794.09,1661.5 1794.09,1578.72 1745.88,1530.5 1745.88,1409.43 J26.1@1803.16,1352.15 R96.1@1803.16,1212.48
  L3_SIG1 w9.4: J26.1@1803.16,1352.15 1626.82,1528.48 1626.82,2382.1 1805.84,2561.12 v6(1859.16,2561.12)
NetC14_2: C14.2 J2.3 U3.8 | length 361.3
  Top Layer w6: v6(923.97,481.5) 923.97,461.93 910.7,448.66 910.7,322.72 930.78,302.64 947.16,302.64 954.13,295.67 J2.3@954.13,247.35
  Top Layer w8: v6(923.97,481.5) U3.8@923.97,528.33
  Bottom Layer w8: v6(923.97,481.5) C14.2@923.97,528.7
NetC15_2: C15.2 J2.2 U3.7 | length 365
  Top Layer w6: U3.7@904.29,528.33 904.29,469.11 v3(894.85,459.68) 894.85,321.4 922.64,293.61 J2.2@922.64,247.35
  Bottom Layer w8: v3(894.85,459.68) 911.1,459.68 922.91,447.86 C15.2@922.91,412.22
NetC17_1: C17.1 C18.1 L5.2 R7.1 | length 174.5
  Top Layer w8: R7.1@504.38,311.6 C18.1@563.43,311.6 C17.1@621.89,311.6 673.03,311.6 L5.2@677.14,307.49
NetC21_1: C21.1 U3.3 Y1.3 | length 532.7
  Top Layer w6: Y1.3@485.16,424.98 553.72,424.98 628.15,350.55 702.35,350.55 v3(800,448.2) 825.55,473.75 U3.3@825.55,528.33
  Bottom Layer w6: v3(800,448.2) 815.8,448.2 825.79,438.21 C21.1@825.79,412.22
NetC22_1: C22.1 U3.2 Y1.1 | length 266
  Top Layer w8: Y1.1@658.39,519.47 v3(707.26,519.47) 751.15,475.57 795.9,475.57 805.86,485.54 U3.2@805.86,528.33
  Bottom Layer w8: C22.1@653.86,519.47 v3(707.26,519.47)
NetC31_1: C31.1 J8.1 R14.2
NetC34_1: C34.1 C35.1 L6.2 R16.1 R17.2 U6.8 U6.9 U7.1
  other v3: 1721.1,3188.39 1715.1,3255.52
NetC38_1: C38.1 C39.1 L7.2 R22.1 R23.2 U8.8 U8.9 U9.1
  other v3: 2278.46,3261.6 2280.47,3308.5
NetC41_1: C41.1 C42.1 C43.1 R36.1 R39.2 R41.2 U11.10 U11.11 U12.1
  other v3: 378.6,3552.6
NetC44_1: C44.1 U11.4 | length 71
  Top Layer w10: C44.1@109.21,3478.86 U11.4@180.17,3478.86
NetC46_1: C46.1 C47.1 C48.1 R44.1 R47.2 R49.2 U13.10 U13.11 U14.1
  other v3: 956.32,3541.07 957.6,3575.6 956.32,3607.54 956.32,3645.76
NetC49_1: C49.1 U13.4 | length 69.3
  Top Layer w6: C49.1@678.46,3475.62 U13.4@747.79,3475.62
NetD1_2: D1.2 R15.1 | length 104.6
  Top Layer w10: R15.1@1851.77,4053.05 1851.77,4155.74 D1.2@1853.12,4157.09
NetD2_2: D2.2 R17.1 | length 170.6
  Top Layer w8: D2.2@1514.89,3255.52 1573.73,3255.52 1586.66,3242.59 1586.66,3205.9 1598.04,3194.52 R17.1@1638.75,3194.52
NetD3_2: D3.2 R23.1 | length 125.2
  Top Layer w8: D3.2@2063.9,3205.9 2188.68,3205.9 R23.1@2188.98,3206.2
NetD4_2: D4.2 R28.2 | length 75.8
  Top Layer w10: R28.2@607.3,4214.95 D4.2@607.3,4290.78
NetD5_2: D5.2 R30.2 | length 93.6
  Top Layer w10: R30.2@607.3,4163.77 635.44,4163.77 655.94,4184.27 D5.2@692.4,4184.27
NetD6_2: D6.2 R33.2 | length 95.8
  Top Layer w10: R33.2@607.3,4106.27 631.53,4106.27 657.3,4080.5 D6.2@692.4,4080.5
NetD7_2: D7.2 R35.2 | length 83.3
  Top Layer w10: D7.2@607.3,3971.58 R35.2@607.3,4054.91
NetD8_2: D8.2 R41.1 | length 74.4
  Top Layer w10: D8.2@463.59,3478.19 R41.1@463.59,3552.6
NetD9_2: D9.2 R49.1
NetD10_1: D10.1 R99.2 | length 93.9
  Top Layer w8: D10.1@1794.09,1740.24 v3(1794.09,1787.2)
  Bottom Layer w8: R99.2@1794.09,1740.24 v3(1794.09,1787.2)
NetD11_1: D11.1 R100.2 | length 111.3
  Top Layer w8: D11.1@1899.09,1740.24 v3(1899.09,1795.88)
  Bottom Layer w8: R100.2@1899.09,1740.24 v3(1899.09,1795.88)
NetD12_1: D12.1 R101.2 | length 103.2
  Top Layer w8: v3(2003.73,1791.7) 2003.73,1740.6 D12.1@2004.09,1740.24
  Bottom Layer w8: v3(2003.73,1791.7) 2003.73,1740.6 R101.2@2004.09,1740.24
NetD13_1: D13.1 R102.2 | length 104.7
  Top Layer w8: D13.1@2109.09,1740.24 2110.18,1741.33 v3(2110.18,1792.14)
  Bottom Layer w8: R102.2@2109.09,1740.24 2110.18,1741.33 v3(2110.18,1792.14)
NetD14_1: D14.1 R103.2 | length 104.8
  Top Layer w8: D14.1@2219.09,1740.24 2219.65,1740.79 v3(2219.65,1792.4)
  Bottom Layer w8: R103.2@2219.09,1740.24 2219.65,1740.79 v3(2219.65,1792.4)
NetJ7_1: J7.1 R14.1
NetJ12_1: J12.1 R60.1 | length 94.8
  Top Layer w8: R60.1@2269.29,578.73 2298.23,578.73 2304.8,585.3 J12.1@2361.39,585.3
NetJ12_2: J12.2 J13.1 | length 503.7
  Top Layer w10: J13.1@2424.45,150.93 2424.45,262.72 2526.6,364.88 2526.6,520.09 J12.2@2461.39,585.3
NetL3_1: L3.1 U3.4 | length 103.3
  Top Layer w8: L3.1@844.91,425.16 845.23,425.49 U3.4@845.23,528.33
NetL4_1: L4.1 U3.9 | length 101.7
  Top Layer w8: L4.1@943.66,427.09 943.97,427.09 943.97,528.01 U3.9@943.66,528.33
NetL6_1: L6.1 U6.7
NetL7_1: L7.1 U8.7
NetR6_2: R6.2 U3.6 | length 125.4
  Top Layer w8: v3@884.6,482.7 v3(884.6,487.77) U3.6@884.6,528.33
  Bottom Layer w8: R6.2@874.4,412.22 874.4,477.57 v3(884.6,487.77)
NetR7_2: R7.2 R8.1 R9.2 | length 1226.8
  Top Layer w8: R7.2@504.38,264.35 504.38,219.72 v3(514.47,209.62) ; R8.1@1042.08,389.98 R9.2@1097.98,389.98 v3(1123.92,389.98)
  Bottom Layer w8: v3(514.47,209.62) 558.45,165.65 1194.82,165.65 1241.85,212.68 1241.85,393.15 1216.2,418.8 1152.74,418.8 v3(1123.92,389.98)
NetR8_2: R8.2 U3.14 | length 91.1
  Top Layer w8: R8.2@1042.08,437.22 U3.14@1042.08,528.33
NetR11_1: R11.1 R13.2 U5.4 | length 143
  Top Layer w6: U5.4@454.84,854.43 R11.1@546.28,854.43 R13.2@546.28,906
NetR19_2: R19.2 U6.6 | length 146.9
  Top Layer w10: R19.2@1414.49,3526.82 1469.52,3526.82 1501.37,3558.67 U6.6@1501.37,3605.53
NetR25_2: R25.2 U8.6 | length 140.4
  Top Layer w10: R25.2@1964.78,3509.56 1965.44,3508.9 2029,3508.9 2045.62,3525.52 U8.6@2045.62,3577.96
NetR27_2: R27.2 U10.4 | length 124.8
  Top Layer w10: R27.2@102.92,4182.86 141.92,4182.86 167.51,4157.27 U10.4@217.1,4157.27
NetR28_1: R28.1 U10.13 | length 134.6
  Top Layer w10: U10.13@449.39,4157.27 483.52,4157.27 541.2,4214.95 R28.1@560.06,4214.95
NetR29_2: R29.2 U10.5 | length 114.2
  Top Layer w10: R29.2@102.92,4131.59 103.02,4131.68 U10.5@217.1,4131.68
NetR30_1: R30.1 U10.12 | length 124
  Top Layer w10: U10.12@449.39,4131.68 496.65,4131.68 528.74,4163.77 R30.1@560.06,4163.77
NetR32_2: R32.2 U10.6 | length 126.4
  Top Layer w10: R32.2@102.92,4076.59 137.31,4076.59 166.81,4106.09 U10.6@217.1,4106.09
NetR33_1: R33.1 U10.11 | length 110.7
  Top Layer w10: U10.11@449.39,4106.09 559.88,4106.09 R33.1@560.06,4106.27
NetR34_2: R34.2 U10.7 | length 137.4
  Top Layer w10: R34.2@102.92,4024.4 124.1,4024.4 180.2,4080.5 U10.7@217.1,4080.5
NetR35_1: R35.1 U10.10 | length 121.3
  Top Layer w10: U10.10@449.39,4080.5 498.73,4080.5 524.32,4054.91 R35.1@560.06,4054.91
NetR37_2: R37.2 U11.1 U11.2
NetR38_1: R38.1 R42.2 U11.9 | length 473.2
  Top Layer w10: U11.9@258.91,3498.54 306.56,3498.54 R42.2@307.38,3499.36 v3(307.38,3474.62) ; R38.1@588.5,3608.72 v3(620,3608.72)
  Bottom Layer w10: v3(307.38,3474.62) 485.9,3474.62 v3(620,3608.72)
NetR38_2: R38.2 R39.1 R43.2
NetR45_2: R45.2 U13.1 U13.2
NetR46_1: R46.1 R50.2 U13.9 | length 473
  Top Layer w8: R46.1@1156.12,3605.49 v3(1187.9,3605.49)
  Top Layer w10: U13.9@826.53,3495.3 898.85,3495.3 R50.2@899.09,3495.54 v3(899.09,3471.34)
  Bottom Layer w10: v3(899.09,3471.34) 1053.75,3471.34 v3(1187.9,3605.49)
NetR46_2: R46.2 R47.1 R51.2
NetR57_1: R57.1 S1.3 S1.4 | length 247.7
  Top Layer w8: R57.1@2351.92,1033.87 2382.78,1033.87 2388.72,1027.93 2435.73,1027.93 S1.4@2435.77,1027.96 S1.3@2435.77,1189.38
NetR58_1: R58.1 Y2.1 | length 74.9
  Top Layer w8: R58.1@2095.29,580.73 2119.88,580.73 2136.22,597.07 Y2.1@2163.43,597.07
NetR60_2: R60.2 Y2.3 | length 63.6
  Top Layer w8: Y2.3@2206.74,628.57 2234.56,628.57 2237.15,625.97 R60.2@2269.29,625.97
NetR69_1: R69.1 S2.3 S2.4 | length 247.9
  Top Layer w8: S2.3@2501.73,1268.15 S2.4@2501.73,1429.56 2538.19,1429.56 2549.95,1417.8 R69.1@2583.32,1417.8
NetR79_1: R79.1 S3.3 S3.4 | length 268.5
  Top Layer w10: S3.3@2513.63,3329.22 2478.35,3364.51 2478.35,3455.36 S3.4@2513.63,3490.64 2552.11,3490.64 2558.02,3484.73 R79.1@2589.04,3484.73
NetR89_1: R89.1 S4.3 S4.4 | length 265.4
  Top Layer w10: S4.3@2526.71,3555.35 2502.4,3579.66 2502.4,3692.46 S4.4@2526.71,3716.76 2565.89,3716.76 2571.79,3710.86 R89.1@2608.12,3710.86
P/VS1: J23.47 J28.3 | length 2076.5
  Top Layer w7.3: v6(1994.51,2509.62) J23.47@2049.02,2509.62
  L3_SIG1 w8: J28.3@1864.72,816.12 1915.03,866.42 1915.03,977.6 2104.56,1167.14 2153.96,1167.14 2266.7,1279.88 2266.7,1893.45 1990.35,2169.8 1990.35,2404.12 1969.95,2424.52 1969.95,2485.06 v6(1994.51,2509.62)
P/VS2: J23.49 J28.5 | length 1936.7
  Top Layer w7.3: v6(1994.51,2446.63) J23.49@2049.02,2446.63
  L3_SIG1 w8: J28.5@1964.72,816.12 2014.65,866.05 2014.65,983.68 2283.43,1252.45 2283.43,1899.77 2005.35,2177.85 2005.35,2435.79 v6(1994.51,2446.63)
P/VS3: J23.50 J28.7 | length 1831.6
  Top Layer w7.3: J23.50@2049.02,2415.13 v6(2103.52,2415.13)
  L3_SIG1 w8: J28.7@2064.72,816.12 2114.93,866.32 2114.93,964.45 2299.07,1148.6 2299.07,1913.68 2103.52,2109.23 v6(2103.52,2415.13)
P/VS4: J23.46 J28.1 | length 2188.8
  Top Layer w7.3: v6(1994.51,2541.12) J23.46@2049.02,2541.12
  L3_SIG1 w8: J28.1@1764.72,816.12 1814.5,865.9 1814.5,984.85 2027.28,1197.62 2142.95,1197.62 2249.75,1304.43 2249.75,1882.82 1975.35,2157.23 1975.35,2390.88 1952.35,2413.88 1952.35,2498.96 v6(1994.51,2541.12)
